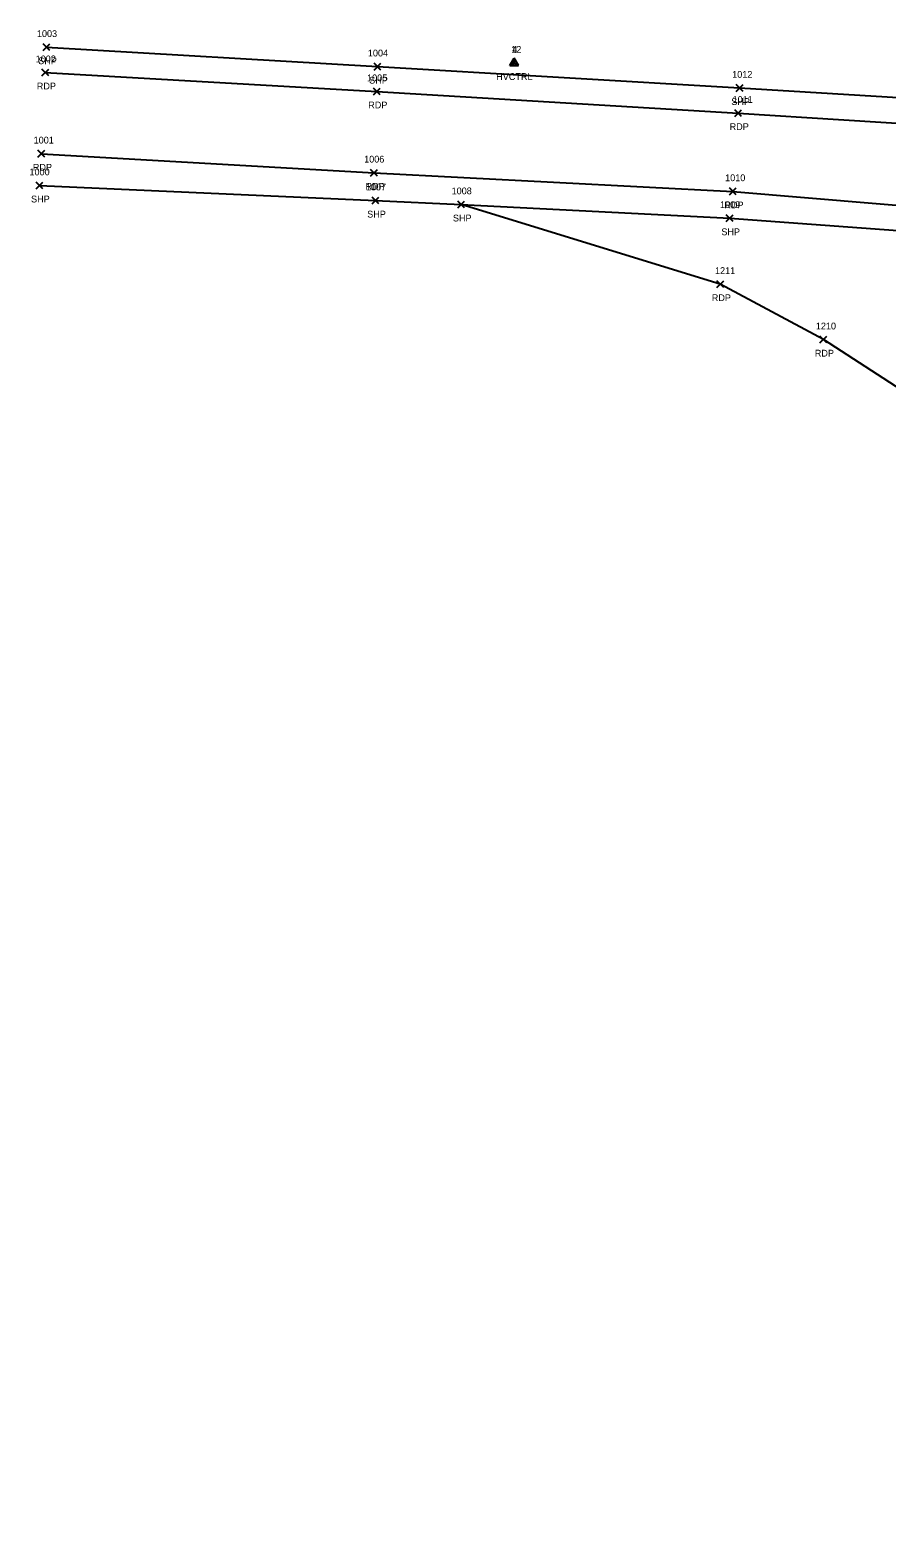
# Model space of a CAD drawing. Extents: x 1519347 to 1522636, y 378779 to 379832.
# Drawn here: x 1520495.8 to 1520748.2, y 379275.3 to 379719.6 of the extents above; entities that cross this region are included whole.
import ezdxf

# ---------------------------------------------------------------- set-up
doc = ezdxf.new("R2010")
doc.units = 0
for name, color, linetype in [('C_A', 7, 'Continuous'), ('C_I', 7, 'Continuous'), ('CPSM', 7, 'Continuous'), ('P_A', 7, 'Continuous'), ('P_I', 7, 'Continuous'), ('P_TIC', 7, 'Continuous'), ('PE', 7, 'Continuous'), ('PET', 7, 'Continuous'), ('PSP', 7, 'Continuous')]:
    doc.layers.add(name, color=color, linetype=linetype)

msp = doc.modelspace()

# ---------------------------------------------------------------- linework, layer by layer
at = {"layer": 'CPSM'}
for p, q in [((1520637.17, 379709.21), (1520638.42, 379711.37)), ((1520637.17, 379709.19), (1520638.42, 379711.35)), ((1520637.17, 379709.21), (1520638.43, 379709.93)), ((1520637.17, 379709.19), (1520638.42, 379709.91)), ((1520639.67, 379709.21), (1520638.42, 379711.37)), ((1520638.43, 379709.93), (1520638.42, 379711.37)), ((1520639.67, 379709.19), (1520638.42, 379711.35)), ((1520638.42, 379709.91), (1520638.42, 379711.35)), ((1520638.42, 379709.91), (1520638.42, 379709.91)), ((1520638.42, 379709.91), (1520639.67, 379709.19)), ((1520638.43, 379709.93), (1520638.43, 379709.93)), ((1520638.43, 379709.93), (1520639.67, 379709.21)), ((1520637.17, 379709.21), (1520639.67, 379709.21)), ((1520637.17, 379709.19), (1520639.67, 379709.19))]:
    msp.add_line(p, q, dxfattribs=at)
at = {"layer": 'P_TIC'}
for points in [[(1520499.66, 379713.58), (1520501.66, 379715.58)], [(1520501.66, 379713.58), (1520499.66, 379715.58)], [(1520597.16, 379707.86), (1520599.16, 379709.86)], [(1520599.16, 379707.86), (1520597.16, 379709.86)], [(1520499.29, 379706.13), (1520501.29, 379708.13)], [(1520501.29, 379706.13), (1520499.29, 379708.13)], [(1520596.92, 379700.55), (1520598.92, 379702.55)], [(1520598.92, 379700.55), (1520596.92, 379702.55)], [(1520703.83, 379701.57), (1520705.83, 379703.57)], [(1520705.83, 379701.57), (1520703.83, 379703.57)], [(1520703.39, 379694.17), (1520705.39, 379696.17)], [(1520705.39, 379694.17), (1520703.39, 379696.17)], [(1520498.12, 379682.2), (1520500.12, 379684.2)], [(1520500.12, 379682.2), (1520498.12, 379684.2)], [(1520596.12, 379676.59), (1520598.12, 379678.59)], [(1520598.12, 379676.59), (1520596.12, 379678.59)], [(1520497.56, 379672.83), (1520499.56, 379674.83)], [(1520499.56, 379672.83), (1520497.56, 379674.83)], [(1520596.58, 379668.39), (1520598.58, 379670.39)], [(1520598.58, 379668.39), (1520596.58, 379670.39)], [(1520701.85, 379671.1), (1520703.85, 379673.1)], [(1520703.85, 379671.1), (1520701.85, 379673.1)], [(1520621.82, 379667.23), (1520623.82, 379669.23)], [(1520623.82, 379667.23), (1520621.82, 379669.23)], [(1520700.9, 379663.18), (1520702.9, 379665.18)], [(1520702.9, 379663.18), (1520700.9, 379665.18)], [(1520698.13, 379643.75), (1520700.13, 379645.75)], [(1520700.13, 379643.75), (1520698.13, 379645.75)], [(1520728.49, 379627.42), (1520730.49, 379629.42)], [(1520730.49, 379627.42), (1520728.49, 379629.42)]]:
    msp.add_lwpolyline(points, dxfattribs=at)
at = {"layer": 'PE'}
for points in [[(1520500.29, 379707.13), (1520597.92, 379701.55), (1520704.39, 379695.17), (1520766.67, 379691.18), (1520865.72, 379682.95), (1520944.87, 379673.83), (1521043.86, 379659.67), (1521144.22, 379641.18), (1521240.97, 379619.56), (1521339.55, 379594.81), (1521436.37, 379566.43), (1521529.39, 379535.32), (1521632.62, 379496.8)], [(1520499.12, 379683.2), (1520597.12, 379677.59), (1520702.85, 379672.1), (1520767.36, 379666.64), (1520862.37, 379658.78), (1520941.16, 379649.92), (1521039.54, 379635.66), (1521138.91, 379617.62), (1521235.57, 379596.13), (1521333.44, 379571.25), (1521428.97, 379543.22), (1521521.96, 379512.45), (1521622.97, 379474.43)]]:
    msp.add_lwpolyline(points, dxfattribs=at)
at = {"layer": 'PET'}
for points in [[(1520699.13, 379644.75), (1520622.82, 379668.23)], [(1521566.64, 378831.03), (1521543.56, 378872.83), (1521519.09, 378912.94), (1521489.55, 378952.75), (1521455.86, 378990.48), (1521419.87, 379025.89), (1521341.37, 379097.91), (1521290.76, 379143.7), (1521238.48, 379191.54), (1521199.1, 379228.33), (1521145.7, 379275.98), (1521050.75, 379364.16), (1520980.24, 379428.62), (1520906.12, 379495.86), (1520857.57, 379538.26), (1520794, 379586.56), (1520766.68, 379604.35), (1520729.49, 379628.42), (1520699.13, 379644.75)]]:
    msp.add_lwpolyline(points, dxfattribs=at)
at = {"layer": 'PSP'}
for points in [[(1520500.66, 379714.58), (1520598.16, 379708.86), (1520704.83, 379702.57), (1520767.67, 379698.75), (1520866.58, 379691.1), (1520963.04, 379679.86), (1520962.98, 379679.81), (1521045.38, 379667.49), (1521145.9, 379649.23), (1521242.81, 379627.02), (1521341.58, 379601.87), (1521438.52, 379574.01), (1521531.82, 379542.79), (1521635.1, 379503.97)], [(1520498.56, 379673.83), (1520597.58, 379669.39), (1520622.82, 379668.23), (1520701.9, 379664.18), (1520764.8, 379659.6), (1520862, 379650.94), (1520940.1, 379642.46), (1521038.42, 379628.05), (1521137.18, 379609.65), (1521233.6, 379588.29), (1521331.39, 379563.44), (1521426.62, 379535.62), (1521519.02, 379505.15), (1521619.86, 379467.25)]]:
    msp.add_lwpolyline(points, dxfattribs=at)

# ---------------------------------------------------------------- texts
at = {"layer": 'C_A'}
for p in [(1520633.11, 379704.91), (1520633.12, 379704.93)]:
    msp.add_text('HVCTRL', height=2, dxfattribs=at).set_placement(p)
at = {"layer": 'C_I'}
for s, p in [('12', (1520637.53, 379712.93)), ('4', (1520637.85, 379712.91))]:
    msp.add_text(s, height=2, dxfattribs=at).set_placement(p)
at = {"layer": 'P_A'}
for s, p in [('SHP', (1520498.2, 379709.58)), ('SHP', (1520595.7, 379703.86)), ('RDP', (1520497.78, 379702.13)), ('RDP', (1520595.41, 379696.55)), ('SHP', (1520702.37, 379697.57)), ('RDP', (1520701.88, 379690.17)), ('RDP', (1520496.61, 379678.2)), ('RDP', (1520594.61, 379672.59)), ('SHP', (1520496.09, 379668.83)), ('SHP', (1520595.11, 379664.39)), ('SHP', (1520620.36, 379663.23)), ('RDP', (1520700.33, 379667.1)), ('SHP', (1520699.44, 379659.18)), ('RDP', (1520696.62, 379639.75)), ('RDP', (1520726.97, 379623.42))]:
    msp.add_text(s, height=2, dxfattribs=at).set_placement(p)
at = {"layer": 'P_I'}
for s, p in [('1003', (1520497.81, 379717.58)), ('1002', (1520497.44, 379710.13)), ('1004', (1520595.31, 379711.86)), ('1005', (1520595.07, 379704.55)), ('1012', (1520702.63, 379705.57)), ('1011', (1520702.75, 379698.17)), ('1001', (1520496.84, 379686.2)), ('1000', (1520495.62, 379676.83)), ('1006', (1520594.21, 379680.59)), ('1007', (1520594.73, 379672.39)), ('1010', (1520700.55, 379675.1)), ('1008', (1520619.97, 379671.23)), ('1009', (1520699.04, 379667.18)), ('1211', (1520697.57, 379647.75)), ('1210', (1520727.27, 379631.42))]:
    msp.add_text(s, height=2, dxfattribs=at).set_placement(p)

doc.saveas('drawing.dxf')
